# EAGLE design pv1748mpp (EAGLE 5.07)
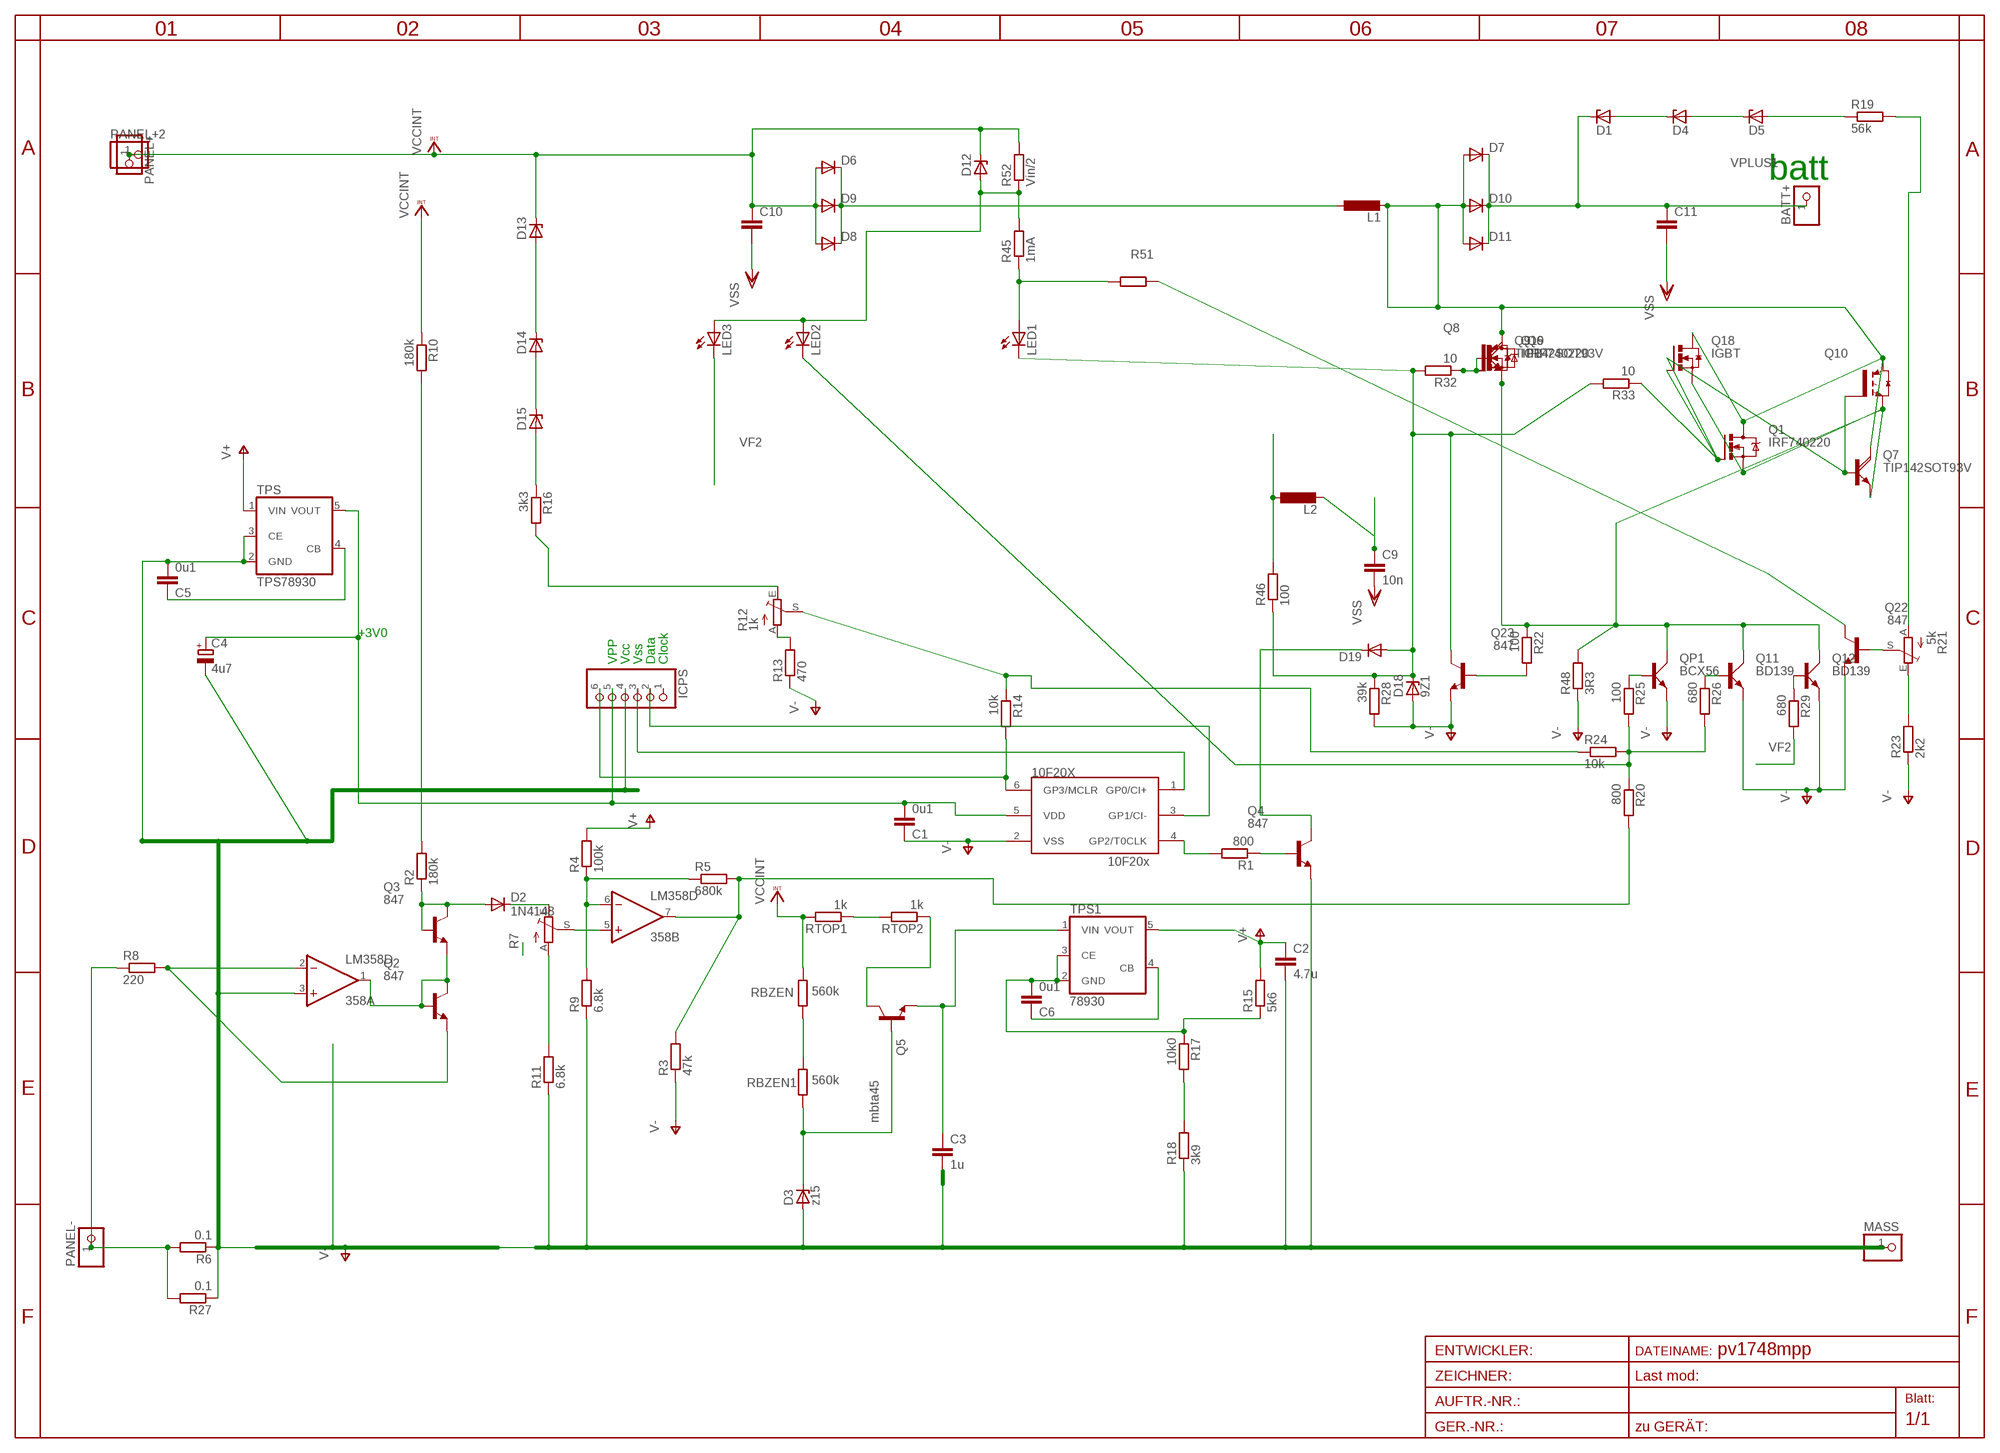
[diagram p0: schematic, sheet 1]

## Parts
10F20X  10F20x  PIC10F204OT  [SOT23-6]
358  LM358D  [SO08]
BATT+  PINHD-1X12MM3  [1X2MM3]
C1  0u1  C-EUC1206  [C1206]
C2  4.7u  C-EUC1206  [C1206]
C3  1u  C-EUC1206  [C1206]
C4  4u7  CPOL-EUSMCA  [SMC_A]
C5  0u1  C-EUC0805  [C0805]
C6  0u1  C-EUC0805  [C0805]
C9  10n  C-EUC0805  [C0805]
C10  C-EU075-052X106  [C075-052X106]
C11  C-EU075-052X106  [C075-052X106]
D1  ZENER-DIODESOD80C  [SOD80C]
D2  1N4148  DIODE-SOD80C  [SOD80C]
D3  z15  ZENER-DIODESOD80C  [SOD80C]
D4  ZENER-DIODESOD80C  [SOD80C]
D5  ZENER-DIODESOD80C  [SOD80C]
D6  DIODE-SMC  [SMC]
D7  DIODE-SMC  [SMC]
D8  DIODE-SMC  [SMC]
D9  DIODE-SMC  [SMC]
D10  DIODE-SMC  [SMC]
D11  DIODE-SMC  [SMC]
D12  ZENER-DIODESOD80C  [SOD80C]
D13  ZENER-DIODESOD80C  [SOD80C]
D14  ZENER-DIODESOD80C  [SOD80C]
D15  ZENER-DIODESOD80C  [SOD80C]
D18  9Z1  ZENER-DIODESOD80C  [SOD80C]
D19  DIODE-MINIMELF  [MINIMELF]
ICPS  PINHD-1X6  [1X06BOX]
L1  L-EUOPEN6  [OPEN6_3]
L2  L-EUOPEN6  [OPEN6_3]
LED1  LEDCHIPLED_1206  [CHIPLED_1206]
LED2  LEDCHIPLED_1206  [CHIPLED_1206]
LED3  LEDCHIPLED_1206  [CHIPLED_1206]
MASS  PINHD-1X12MM3  [1X2MM3]
PANEL+  PINHD-1X11MM6  [1X1MM8]
PANEL+2  PINHD-1X12MM3  [1X2MM3]
PANEL-  PINHD-1X12MM3  [1X2MM3]
Q1  IRF740220  [TO220BV]
Q2  847  BC847ALT1SMD  [SOT23]
Q3  847  BC847ALT1SMD  [SOT23]
Q4  847  BC847ALT1SMD  [SOT23]
Q5  mbta45  BC847ALT1SMD  [SOT23]
Q6  IRF740220  [TO220BV]
Q7  TIP142SOT93V  [SOT93V]
Q8  IRG4BC15UD-S  [D2PACK]
Q9  TIP142SOT93V  [SOT93V]
Q10  IRG4BC15UD-S  [D2PACK]
Q11  BD139  [TO126AV]
Q12  BD139  [TO126AV]
Q18  IGBT  N-HEXFET_DPAK-  [TO252]
Q19  IGBT  N-HEXFET_DPAK-  [TO252]
Q22  847  BC847ASMD  [SOT23]
Q23  847  BC847ASMD  [SOT23]
QP1  BCX56  [SOT223]
R1  800  R-EU_R0805  [R0805]
R2  180k  R-EU_0207/15  [0207/15]
R3  47k  R-EU_R0805  [R0805]
R4  100k  R-EU_R1206  [R1206]
R5  680k  R-EU_R0805  [R0805]
R6  0.1  R-EU_R2010  [R2010]
R7  TRIM_EU-S64W  [S64W]
R8  220  R-EU_R0805  [R0805]
R9  6.8k  R-EU_R1206  [R1206]
R10  180k  R-EU_R1206  [R1206]
R11  6.8k  R-EU_R0805  [R0805]
R12  1k  TRIM_EU-S64W  [S64W]
R13  470  R-EU_R0805  [R0805]
R14  10k  R-EU_R0805  [R0805]
R15  5k6  R-EU_R0805  [R0805]
R16  3k3  R-EU_R0805  [R0805]
R17  10k0  R-EU_R0805  [R0805]
R18  3k9  R-EU_R0805  [R0805]
R19  56k  R-EU_R0805  [R0805]
R20  800  R-EU_R0805  [R0805]
R21  5k  TRIM_EU-S64W  [S64W]
R22  100  R-EU_R0805  [R0805]
R23  2k2  R-EU_R0805  [R0805]
R24  10k  R-EU_R0805  [R0805]
R25  100  R-EU_R0805  [R0805]
R26  680  R-EU_R0805  [R0805]
R27  0.1  R-EU_R3216  [R3216]
R28  39k  R-EU_R0805  [R0805]
R29  680  R-EU_R0805  [R0805]
R32  10  R-EU_R0805  [R0805]
R33  10  R-EU_R0805  [R0805]
R45  1mA  R-EU_R1206  [R1206]
R46  100  R-EU_R0805  [R0805]
R48  3R3  R-EU_R2010  [R2010]
R51  39k  R-EU_R0805  [R0805]
R52  Vin/2  R-EU_R1206  [R1206]
RBZEN  560k  R-EU_R1206  [R1206]
RBZEN1  560k  R-EU_R1206  [R1206]
RTOP1  1k  R-EU_R1206  [R1206]
RTOP2  1k  R-EU_R1206  [R1206]
TPS  TPS78930  TPS78930SOT23-5  [SOT25]
TPS1  78930  TPS78930SOT23-5  [SOT25]

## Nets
BOOST_EN: D19.C Q4.3(C)
CB: D3.C Q5.1(B) RBZEN1.2
DQ18: D7.A D10.A D11.A L1.2 Q1.D Q6.D Q7.C Q8.2(C) Q9.C Q10.2(C) Q18.3(D) Q19.3(D)
GND1: C6.1 TPS1.4(CB)
IN-: PANEL-.1 R6.2 R8.1 R27.2
L2DOT: C9.1 L2.2
L2NO: L2.1 R46.2
N$1: Q4.1(B) R1.1
N$2: R7.A R11.2
N$3: R12.S R14.1 R24.1
N$4: 10F20X.1(GP0/CI+) ICPS.3
N$5: 10F20X.4(GP2/T0CLK) R1.2
N$6: R2.2 R10.2
N$7: 358.1(A:OUT) Q2.1(B) Q2.3(C) Q3.2(E)
N$8: 10F20X.3(GP1/CI-) ICPS.2
N$9: 10F20X.5(VDD) C1.2 C4.+ ICPS.5 TPS.5(VOUT)
N$10: 358.2(A:-IN) Q2.2(E) R8.2
N$11: C5.1 TPS.4(CB)
N$12: D2.A Q3.1(B) Q3.3(C) R2.1
N$13: D2.C R7.E
N$15: 358.5(B:+IN) R7.S
N$16: Q5.3(C) RTOP2.1
N$17: 358.6(B:-IN) R4.1 R5.1 R9.2
N$18: D15.A R16.1
N$19: RBZEN1.1 RBZEN.2
N$20: LED1.A R45.1 R51.1
N$21: Q23.1(B) R22.2
N$22: D5.A R19.1
N$23: D14.A D15.C
N$24: D13.A D14.C
N$25: R12.E R16.2
N$26: R12.A R13.2
N$27: QP1.1(B) R25.1
N$28: R17.2 R18.2
N$29: RTOP1.1 RTOP2.2
N$30: D4.A D5.C
N$31: D1.A D4.C
N$32: R19.2 R21.A
N$33: 358.7(B:OUT) R3.2 R5.2 R20.2
N$34: R21.E R23.2
N$35: Q11.B R26.1
N$36: Q12.B R29.1
N$56: Q1.G Q7.B Q10.1(G) Q18.1(G) R33.1
N$58: Q6.G Q8.1(G) Q9.B Q19.1(G) R32.1
N$71: Q22.3(C) R51.2
N$80: D12.A LED2.A LED3.A R45.2 R52.1
N$89: LED2.C R20.1 R24.2 R25.2 R26.2
NODOTL2: D6.C D8.C D9.C L1.1
PGATE: D18.C D19.A LED1.C Q23.3(C) R28.1 R32.2 R33.2 R46.1
PIR: 10F20X.6(GP3/MCLR) ICPS.6 R14.2
PRB1: Q22.1(B) R21.S
SFET1: Q1.S Q6.S Q7.E Q8.3(E) Q9.E Q10.3(E) Q11.C Q12.C Q18.2(S) Q19.2(S) QP1.2(C) R22.1 R48.2
V15: C3.1 Q5.2(E) TPS1.1(VIN)
V+: C2.1 R4.2 R15.2 TPS1.5(VOUT) TPS.1(VIN)
V-: 10F20X.2(VSS) 358.3(A:+IN) C1.1 C2.2 C3.2 C4.- C5.2 C9.2 C10.2 C11.2 D3.A D18.A ICPS.4 MASS.1 Q4.2(E) Q11.E Q12.E Q22.2(E) Q23.2(E) QP1.3(E) R3.1 R6.1 R9.1 R11.1 R13.1 R18.1 R23.1 R27.1 R28.2 R48.1 TPS.2(GND) TPS.3(CE) ; supply symbol labelled VSS
VCCINT: C10.1 D6.A D8.A D9.A D12.C D13.C PANEL+2.1 PANEL+.1 R10.1 R52.2 RBZEN.1 RTOP1.2
VF2: LED3.C R29.2
VPLUS1: BATT+.1 C11.1 D1.C D7.C D10.C D11.C
X: C6.2 R15.1 R17.1 TPS1.2(GND) TPS1.3(CE)
Unconnected: ICPS.1

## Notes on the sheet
- batt
- +3V0
- VPP | Vcc | Vss | Data | Clock

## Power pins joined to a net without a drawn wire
V+: 358.8(P:V+)
V-: 358.4(P:V-)

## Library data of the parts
10F20X = microchip-3:PIC10F2*: uPC nW 0,25/0,5k Program Flash memory Comparator
358 = linear:LM358: OP AMP also LM158; LM258; LM2904 Source: http://cache.national.com/ds/LM/LM158.pdf
BATT+ MASS PANEL+ PANEL+2 PANEL- = pinhead:PINHD-1X1: PIN HEADER
C1-C3 C5 C6 C9-C11 = rcl:C-EU: CAPACITOR, European symbol
C4 = rcl(2):CPOL-EU: POLARIZED CAPACITOR, European symbol
D1 D3-D5 D12-D15 D18 = diode:ZENER-DIODE: Z-Diode
D2 D6-D11 D19 = diode:DIODE-: DIODE
ICPS = pinhead:PINHD-1X6: PIN HEADER
L1 L2 = rcl:L-EU: INDUCTOR, European symbol
LED1-LED3 = led:LED: LED
Q1 Q6 = transistor-power:IRF740: N-CHANNEL MOS FET
Q2-Q5 Q22 Q23 = transistor-npn:BC847*: NPN Transistor
Q7 Q9 = transistor-power:TIP142: NPN DARLINGTON TRANSISTOR
Q8 Q10 = transistor-power:IRG4BC15UD-: INSULATED GATE BIPOLAR TRANSISTOR WITH ULTRAFAST SOFT RECOVERY DIODE
Q11 Q12 = transistor-power:BD139: NPN TRANSISTOR
Q18 Q19 = transistor-power:N-HEXFET_?-*: HEXFET® Power MOSFET
QP1 = transistor-power:BCX56
R1-R6 R8-R11 R13-R20 R22-R29 RBZEN RBZEN1 RTOP1 RTOP2 = rcl:R-EU_: RESISTOR, European symbol
R7 R12 R21 = pot:TRIM_EU-: POTENTIOMETER
R32 R33 R45 R46 R48 R51 R52 = rcl-2:R-EU_: RESISTOR, European symbol
TPS TPS1 = v-reg:TPS78930

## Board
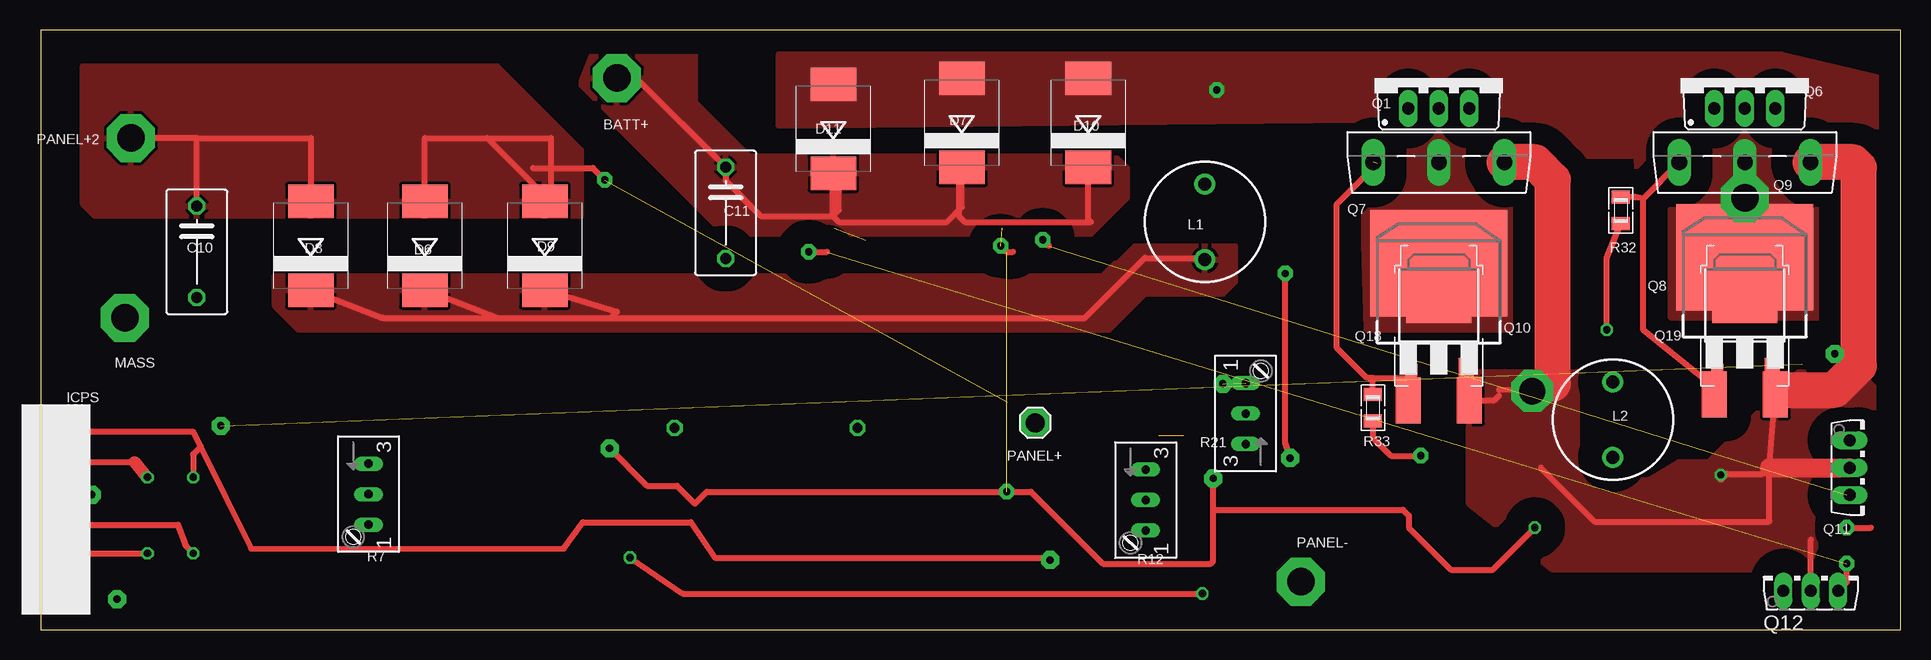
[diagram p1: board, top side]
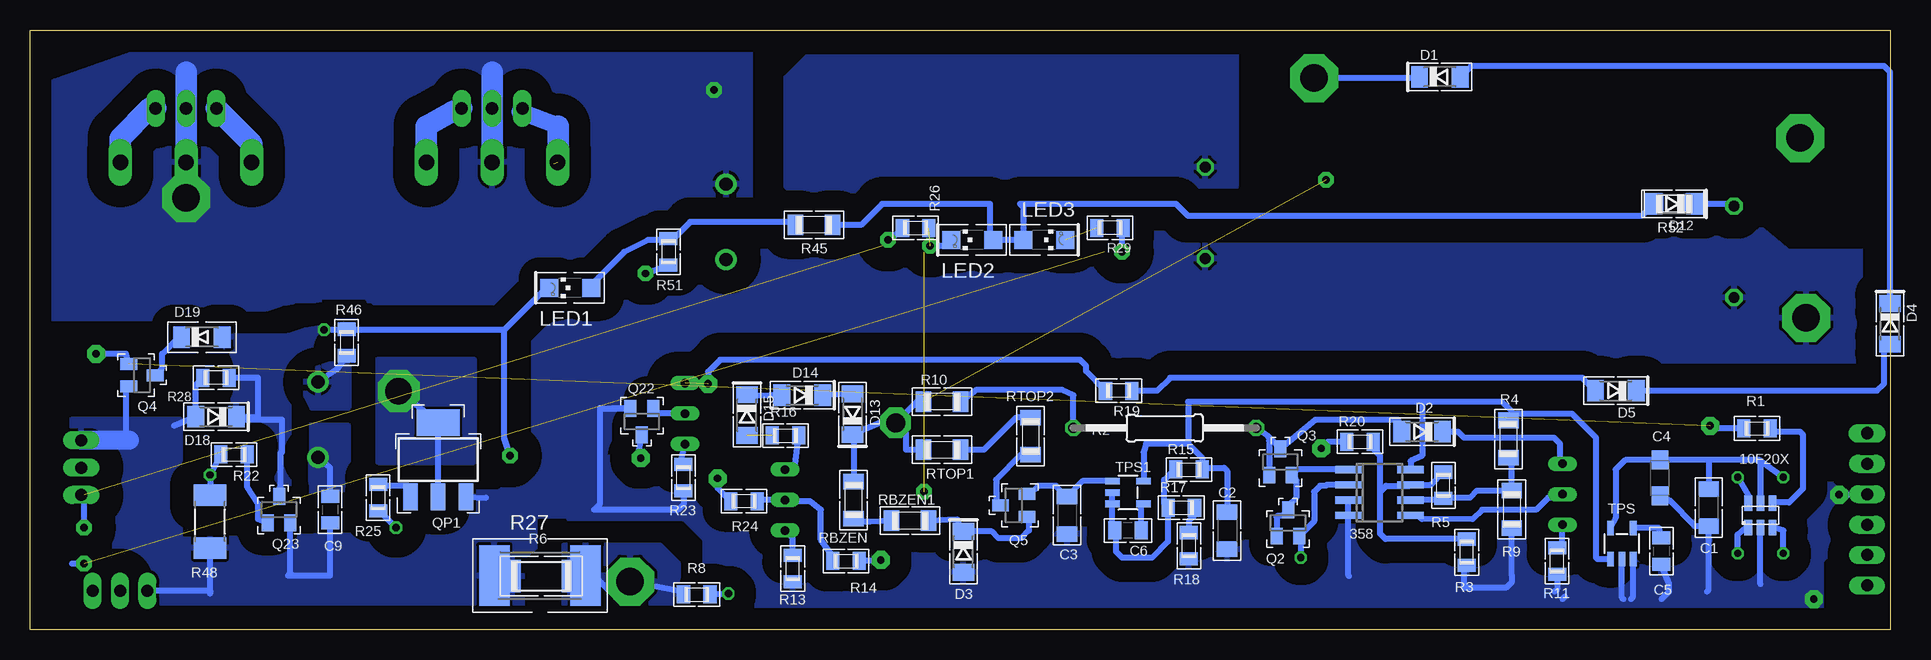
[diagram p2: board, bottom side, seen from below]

Size 155 x 50 mm. Coordinates in mm from the lower left corner, seen from the top.
Outline: 0,0 155,0 155,50 0,50 0,0
Copper layers (1*16): Top 0.035mm / dielectric 1.5mm / Bottom 0.035mm
Design rules "default *": minimum track width 10mil, minimum drill 24mil, track to track 8mil, track to pad 8mil, pad to pad 8mil, via to via 8mil, smd to smd 8mil, copper to edge 30mil, drill to drill 8mil, minimum pad ring 10mil, minimum via ring 8mil, stop-mask expansion 4mil, vias tented up to drill 0mil, thermal gap 10mil

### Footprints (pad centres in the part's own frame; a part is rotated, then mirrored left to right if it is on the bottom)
SOT23-6 = smd 0.635 x 1.27: 1 -1.016,-1.016; 2 0,-1.016; 3 1.016,-1.016; 4 1.016,1.016; 5 0,1.016; 6 -1.016,1.016
SO08 = smd 0.6 x 2.2: 1 -1.905,-2.6; 2 -0.635,-2.6; 3 0.635,-2.6; 4 1.905,-2.6; 5 1.905,2.6; 6 0.635,2.6; 7 -0.635,2.6; 8 -1.905,2.6
1X2MM3 = drill 2.3 pad 4 octagon: 1 0,0
C1206 = smd 1.3 x 1.7: 1 -1.55,0; 2 1.55,0
SMC_A = smd 1.6 x 1.4: + -1.5,0; - 1.5,0
C0805 = smd 1.1 x 1.5: 1 -1.1,0; 2 1.1,0
C075-052X106 = drill 0.914 octagon: 1 -3.81,0; 2 3.81,0
SOD80C = smd 1.4 x 1.8: A 1.7,0; C -1.7,0
SMC = smd 2.8 x 3.8: A 3.7,0; C -3.7,0
MINIMELF = smd 1.4 x 1.8: A 1.7,0; C -1.7,0
1X06BOX = drill 1 long: 1 -6.35,0; 2 -3.81,0; 3 -1.27,0; 4 1.27,0; 5 3.81,0 | drill 1.016 long: 6 6.35,0
OPEN6_3 = drill 1.1 pad 1.778 round: 1 -3.15,0; 2 3.15,0
CHIPLED_1206 = smd 1.5 x 1.5: A 0,-1.75; C 0,1.75
1X1MM8 = drill 1.6 pad 2.54 octagon: 1 0,0
TO220BV = drill 1.016 long: D 0,-2.54; G -2.54,-2.54; S 2.54,-2.54
SOT23 = smd 1 x 1.4: 1 -0.95,-1.1; 2 0.95,-1.1; 3 0,1.1
SOT93V = drill 1.3 pad 1.676 long: B -5.461,-2.54; C 0,-2.54; E 5.461,-2.54
D2PACK = smd 2.083 x 3.81: 1 -2.54,-8.89; 3 2.54,-8.89 | smd 11.43 x 8.89: 2 0,2.54
TO126AV = drill 1 pad 1.27 long: B 2.286,-1.27; C 0,-1.27; E -2.286,-1.27
TO252 = smd 1 x 1.6: 1 -2.28,-3.53 | smd 1.27 x 2.54: 2 2.28,-3.53 | smd 5.4 x 6.2: 3 0,3.77
SOT223 = smd 1.219 x 2.235: 1 -2.311,-3.099; 2 0,-3.099; 3 2.311,-3.099 | smd 3.6 x 2.2: 4 0,3.099
R0805 = smd 1.1 x 1.5: 1 -1.1,0; 2 1.1,0
0207/15 = drill 0.813 octagon: 1 -7.62,0; 2 7.62,0
R1206 = smd 1.3 x 1.7: 1 -1.55,0; 2 1.55,0
R2010 = smd 1.4 x 2.7: 1 -2.4,0; 2 2.4,0
S64W = drill 0.7 long: A 2.54,1.27; E -2.54,1.27; S 0,1.27
R3216 = smd 2.54 x 5.08: 1 -3.81,0; 2 3.81,0
R2010' = smd 1.8 x 2.7: 1 -2.2,0; 2 2.2,0
SOT25 = smd 0.55 x 1.2: 1 -0.95,-1.3; 2 0,-1.3; 3 0.95,-1.3; 4 0.95,1.3; 5 -0.95,1.3

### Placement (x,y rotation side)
10F20X  10.79,9.53 0 bottom
358  42.55,11.43 270 bottom
BATT+  48,46 0 top
C1  15.11,10.16 90 bottom
C2  55.24,8.26 270 bottom
C3  68.58,9.53 270 bottom
C4  19.18,12.63 270 bottom
C5  19.05,6.54 270 bottom
C6  63.5,8.26 180 bottom
C9  130,10 270 bottom
C10  13,31.5 270 top
C11  57.06,34.75 270 top
D1  37.51,46.09 0 bottom
D2  39,16.5 180 bottom
D3  77.22,6.48 270 bottom
D4  0,25.5 270 bottom
D5  22.84,19.91 180 bottom
D6  32,32 90 top
D7  76.77,42.25 90 top
D8  22.5,32 90 top
D9  42,32 90 top
D10  87.29,42.25 90 top
D11  66.05,41.75 90 top
D12  18,35.5 180 bottom
D13  86.45,17.96 90 bottom
D14  90.65,19.55 180 bottom
D15  95.27,17.88 270 bottom
D18  139.5,17.75 180 bottom
D19  140.67,24.38 0 bottom
ICPS  1.91,10.02 90 top
L1  97,34 90 top
L2  131,17.5 270 top
LED1  110,28.5 90 bottom
LED2  76.5,32.5 90 bottom
LED3  70.5,32.5 270 bottom
MASS  7,26 0 top
PANEL+  82.86,17.24 0 top
PANEL+2  7.5,41 0 top
PANEL-  105,4 0 top
Q1  116.5,46 0 top
Q2  50.16,8.89 0 bottom
Q3  50.8,13.97 0 bottom
Q4  145.67,21.2 270 bottom
Q5  73.03,10.35 90 bottom
Q6  142,46 0 top
Q7  116.5,41.5 0 top
Q8  142,28.5 0 top
Q9  142,41.5 0 top
Q10  116.5,28 0 top
Q11  152,13.5 270 top
Q12  147.5,4.5 0 top
Q18  116.5,24.9 0 top
Q19  142,24.9 0 top
Q22  104.01,17.34 180 bottom
Q23  134.25,10 0 bottom
QP1  120.98,14.16 0 bottom
R1  11.08,16.77 0 bottom
R2  60.44,16.81 180 bottom
R3  35.27,6.45 90 bottom
R4  31.8,15.88 90 bottom
R5  37.22,12.03 90 bottom
R6  112.39,4.45 0 bottom
R7  26.04,11.29 270 top
R8  99.44,2.92 0 bottom
R9  31.52,10.03 90 bottom
R10  79,19 0 bottom
R11  27.75,5.71 90 bottom
R12  90.81,10.79 270 top
R13  91.44,5.08 90 bottom
R14  87,5.71 0 bottom
R15  58.42,13.34 0 bottom
R16  92.05,16.18 0 bottom
R17  59.05,10.16 0 bottom
R18  58.42,6.99 90 bottom
R19  64.28,19.91 180 bottom
R20  44.16,15.66 0 bottom
R21  101.68,18.01 90 top
R22  138,14.6 0 bottom
R23  100.55,12.66 90 bottom
R24  95.5,10.7 180 bottom
R25  126,11 270 bottom
R26  81.2,33.5 0 bottom
R27  112.5,4.5 0 bottom
R28  139.5,21 180 bottom
R29  65,33.5 180 bottom
R32  131.66,34.95 270 top
R33  111,18.5 270 top
R45  89.67,33.75 0 bottom
R46  128.61,23.94 270 bottom
R48  3R3  [R2010']  140,9 90 bottom
R51  101.8,31.5 270 bottom
R52  18,35.5 0 bottom
RBZEN  86.36,10.79 270 bottom
RBZEN1  81.66,9.07 0 bottom
RTOP1  79,15 180 bottom
RTOP2  71.62,16.12 90 bottom
TPS  22.35,7.17 0 bottom
TPS1  63.5,11.43 270 bottom

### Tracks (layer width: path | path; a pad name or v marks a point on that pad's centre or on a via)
BOOST_EN
  Bottom 0.5: D19.C 142.62,24.38 144,23 144,21.77 Q4.3
CB
  Bottom 0.5: Q5.1 71.75,9.23 71.75,8.26 72.39,7.62 74.3,7.62 74.85,8.18 D3.C 77.72,9.18 RBZEN1.2
DQ18  (via drill 0.6 pad 1.27, 2.3 pad 4)
  Bottom 1.8: Q7.C Q1.D 116.5,46.5 | Q9.C Q6.D 142,46.5
  other vias: 142,36 98,45
  pour Bottom (isolate 1.8, rank 4): 95,36 95,48.5 145,48.5 153.5,45.5 153.5,26 134.5,26 133,27.5 126.5,27.5 125.5,26.5 111.5,26
  pour Top (isolate 1.8, rank 4, no thermals): 61.5,42 61.5,48 145,48 153.5,46 153.5,26 134.5,26 133.5,27 133,39.5 127.5,39.5 126.5,38.5 126.5,27 124.5,25 110.5,25 110,42.5
GND1
  Bottom 0.5: C6.1 62.4,10.28 TPS1.4
IN-
  Bottom 0.5: R6.2 107.95,4.45 106.68,3.17 PANEL-.1 100.8,3.17 R8.1
  pour Bottom (isolate 2): 101,1 101,5.5 102.5,7 110.5,7 110.5,1.5 110,1
L2DOT
  Bottom 0.5: L2.2 130,13.5 C9.1
  pour Bottom (isolate 2, rank 3, no thermals): 128.5,11 128.5,17 132,17 132,11
L2NO
  Bottom 0.5: R46.2 129.41,21.72 L2.1
  pour Bottom (isolate 2, rank 3): 129,22.5 128.5,22 128.5,18.5 131.5,18.5 132,19.5 132,21.5
N$1  (via drill 0.6 pad 1.5)  (1 unrouted)
  Bottom 0.5: Q4.1 147,23 v149.5,23 | R1.1 14.77,16.77 v15,17
N$2
  Bottom 0.5: R7.A 27.3,7.26 R11.2
N$3
  Bottom 0.5: R14.1 88.09,6.09 89.1,7.5 89.1,10 90,10.7 91.87,10.7 R12.S 94,10.8 R24.1
N$4  (via drill 0.6)
  Top 0.5: ICPS.3 11.43,8.75 12.06,6.99 v12.7,6.35
  Bottom 0.5: v12.7,6.35 12.7,7.9 11.99,8.51 10F20X.1
N$5
  Bottom 0.5: 10F20X.4 9.72,10.6 8.4,10.6 7.24,11.76 7.24,16.24 7.5,16.5 9.71,16.5 R1.2
N$6
  Bottom 0.5: R2.2 68.06,19.56 69,20 76.14,20 R10.2
N$7
  Bottom 0.5: 358.1 49.38,13.34 Q3.2 49.5,12.52 49.5,11 50.16,10.34 Q2.3 50.66,9.5 51,9.5 51.12,9.38 Q2.1
N$8  (via drill 0.6)
  Top 0.5: ICPS.2 3.67,6.21 3.81,6.35 v8.89,6.35
  Bottom 0.5: v8.89,6.35 8.89,8.26 10F20X.3
N$9  (via drill 0.6)
  Top 0.5: 7.81,13.97 2.04,13.97 ICPS.5
  Top 1.016: 7.81,13.97 v8.89,12.7
  Bottom 0.5: 15.24,14.13 10.86,14.13 10.75,14.02 | 15.24,14.13 C4.+ 22.06,14.13 22.86,13.34 22.86,9.3 TPS.5 | v8.89,12.7 10.7,13.97 10.75,14.02 | 10F20X.5 10.79,13.97 10.75,14.02 | C1.2 15.11,14 15.24,14.13
N$10  (via drill 0.6)
  Top 0.5: v96.8,3 53.5,3 v49.1,6
  Bottom 0.5: 358.2 46.94,12.06 47,12 47.5,12 48,11.5 48,9.01 Q2.2 49.1,7.41 v49.1,6 | R8.2 97.08,2.92 v96.8,3
N$11
  Bottom 0.5: TPS.4 19.25,8.47 C5.1
N$12
  Bottom 0.5: D2.A 41,17.5 47.88,17.5 Q3.3 51.62,15.88 | R2.1 51.82,16.09 51.62,15.88 | Q3.1 51.75,15.75 51.62,15.88
N$13
  Bottom 0.5: D2.C 35.99,16.49 35.5,16 28,16 27.5,15.5 27.5,14.03 R7.E
N$15
  Bottom 0.5: 358.5 39.52,9.53 39,9.2 34.77,9.22 34,10 29.5,10 28.5,11 27.59,11 R7.S
N$16
  Bottom 0.5: RTOP2.1 72.43,14.57 74.5,12.5 74.5,10.73 Q5.3
N$17
  Bottom 0.5: 358.6 37.35,10.79 R5.1 37.15,11 35,11 34.42,11.57 R9.2 31.52,14.05 R4.1
N$18  (1 unrouted)
N$19
  Bottom 0.5: RBZEN1.1 83.37,9.07 85,9 86.11,9 RBZEN.2
N$20
  Bottom 0.5: LED1.A 108.25,28.75 105.5,31.5 103.5,32.5 102.5,32.5 101.9,32.5 | 101.9,32.5 R51.1 | R45.1 91.47,34 100,34 101.5,32.5 101.9,32.5
N$21
  Bottom 0.5: R22.2 136.9,11.9 136,10.5 136,9.2 Q23.1
N$22
  Bottom 0.5: D5.A 25.64,21 60,21 61.09,19.91 R19.1
N$23
  Bottom 0.5: D14.A 95.43,19.45 D15.C
N$24
  Bottom 0.5: D13.A D14.C
N$25
  Bottom 0.5: R16.2 91.25,13.76 R12.E
N$26
  Bottom 0.5: R13.2 91.44,7.62 R12.A
N$27
  Bottom 0.5: QP1.1 123.3,11.3 123.5,12 125.6,12 R25.1
N$28
  Bottom 0.5: R18.2 58.42,9.08 58,9.5 58,10.12 R17.2
N$29
  Bottom 0.5: RTOP1.1 75.52,14.98 72.83,17.67 RTOP2.2
N$30
  Bottom 0.5: D4.A 0.5,23.3 0.5,20.5 1.09,19.91 D5.C
N$31
  Bottom 0.5: D1.A 34.9,47 0.5,47 0,46.5 D4.C
N$32  (via drill 0.6 pad 1.5)  (1 unrouted)
  Bottom 0.5: R19.2 67,21.53 67,22 67.5,22.5 97.5,22.5 98.5,21.5 v98.5,20.5
N$33
  Bottom 0.5: R5.2 38.28,12.06 358.7 40.01,12 42,12 42.5,11.5 | R3.2 42.05,7.54 42.5,8 42.5,11.5 | 42.5,11.5 42.5,14.5 43,15 43,15.6 R20.2
N$34
  Bottom 0.5: R21.E 100.75,13.97 R23.2
N$35  (via drill 0.6 pad 1.27)  (1 unrouted)
  Top 0.5: v150.5,8.5 152.5,8.5 | v83.5,32.5 84,32
  Bottom 0.5: Q11.B 150.5,11.21 v150.5,8.5 | R26.1 83.3,32.5 v83.5,32.5
N$36  (via drill 0.6 pad 1.27)  (1 unrouted)
  Top 0.5: v64,31.5 65.5,31.5 | Q12.B 150.5,3.94 v150.5,5.5
  Bottom 0.5: R29.1 64,33.4 v64,31.5 | v150.5,5.5 151.5,5.5
N$56  (1 unrouted)
  Top 0.5: Q10.1 114.06,19.21 Q18.1 113.85,21 111,21 | 111.36,38.86 108,35.5 108,23.5 110.5,21 111,21 | R33.1 111,21
  Bottom 0.5: Q1.G 114.18,43.46 114.18,43.18
  Bottom 1.4: 111,42 114.18,43.18
  Bottom 1.8: 111,42 111,39.86 Q7.B
N$58
  Top 0.5: 133.54,35.93 Q9.B | 133.54,35.93 133.54,24.96 138.5,21 Q19.1 139.59,20.25 Q8.1 | R32.1 132.91,36.05 133.54,35.93
  Bottom 1.8: Q9.B 136.54,40.54 Q6.G
N$71  (via drill 0.6 pad 1.27, 0.6 pad 1.5)
  Top 0.5: v103.7,29.7 103.7,15.6 v104.1,14.3
  Bottom 0.5: v103.7,29.7 R51.2 | v104.1,14.3 104.25,15 Q22.3
N$80
  Bottom 0.5: R52.1 D12.A 20.7,34.5 58.5,34.5 59.5,35.5 72.5,35.5 72.25,35.25 LED3.A LED2.A 75,32.75 75,35.5 84,35.5 85.75,33.75 R45.2
N$89  (via drill 0.6, 0.6 pad 1.27, 0.6 pad 1.5)  (2 unrouted)
  Top 0.5: v47.4,15.1 50.5,12 53,12 54.5,10.5 55.5,11.5 v80.5,11.5 82.5,11.5 88.5,5.5 97.5,5.5 97.7,5.7 97.7,10 | 97.7,10 v97.7,12.6 | v124.5,8.5 121,5 117.5,5 114,8.5 114,9.5 113.5,10 97.7,10 | v80,32 80.5,31.5 81,31.5
  Bottom 0.5: R24.2 97.7,11.8 v97.7,12.6 | v47.4,15.1 46.84,15.66 R20.1 | LED2.C 78.75,32 v80,32 | v124.5,8.5 125.9,9.9 R25.2
NODOTL2
  Top 0.5: D8.C 28.5,26 38,26 | 38,26 47.5,26 | 47.5,26 87,26 92,31 96.85,31 L1.1 | 38,26 D6.C | D9.C 48,26.5 47.5,26
  pour Top (isolate 2, rank 3): 19.5,29.5 88.5,29.5 91,32 99.5,32 99.5,29 98.5,28 92,28 89,25 21.5,25 19.5,27
PGATE  (via drill 0.6, 0.6 pad 1.27)
  Top 0.5: R32.2 130.5,31 v130.5,25 | R33.2 111,16 112.5,14.5 v115,14.5
  Bottom 0.5: R46.1 v130.5,25 115.5,25 | Q23.3 134.25,11.75 134.1,11.8 134.1,14.8 134,14.8 134,17.5 137.8,17.5 D18.C 136,17.75 136,21 R28.1 | v115,14.5 115.5,16 115.5,25 | LED1.C 112,28.5 115.5,25
  pour Bottom (isolate 2, rank 3): 135,11 135,15 136,16 137,16 138.5,17.5 138.5,19.5 139,21.5 139.5,24.5 133.5,24.5 132,25 129,25.5 129,24 133.5,22.5 133.5,11.5
PIR  (via drill 0.6, 0.6 pad 1.5)
  Top 0.5: 13.34,15.24 17.54,6.74 43.58,6.77 45.17,8.95 54.17,8.95 56.17,5.98 83.92,5.98 v84.1,5.8 | 13.34,15.24 12.7,16.51 2.04,16.51 ICPS.6 | v12.7,12.7 12.7,14.61 13.34,15.24
  Bottom 0.5: 10F20X.6 11.81,11.18 v12.7,12.7 | R14.2 84.58,5.71 v84.1,5.8
PRB1
  Bottom 0.5: R21.S 102.99,18.01 Q22.1
SFET1  (via drill 0.6, 2.2 pad 3.5)
  Top 0.5: Q8.3 144.04,13.5 144.04,9.04 144,9 129.5,9 125,13.5 | v140,12.9 140,12.5 140.5,13 143.5,13 144,13.5 | Q19.2 144.16,20.84 145,20 | Q18.2 118.78,19.37 Q10.3 121.11,19.11 121.5,19.5 | v124.28,19.89 121.5,20 | Q12.C 147.5,7.5
  Top 1.6: 144.04,13.5 Q11.C
  Top 3: Q7.E 124.54,38.96 126,37.5 126,20.5 | Q9.E 151.04,38.96 151.5,38.5 151.5,22 149.5,20 145,20
  Bottom 0.5: R48.2 v140,12.9 R22.1 | QP1.2 120.98,17.29 v124.28,19.89
  Bottom 1.8: Q1.S 119.82,43.18 122,42 122,38.93 Q7.E | Q6.S 145.04,43.46 147.5,41 147.5,39 Q9.E
  pour Bottom (no thermals): 126,22.5 126,14 118,14 118,22.5
  pour Top (isolate 2, rank 3): 119,21.5 128,21.5 128,14 129.5,12.5 134,12.5 136.5,14 139,14 146.5,21.5 151.5,21.5 153,20 153,11.5 149.5,5 126,5 119,10.5
V15
  Bottom 0.5: TPS1.1 67.28,12.38 C3.1 69.5,12 71,12 71.7,11.3 Q5.2
V+
  Bottom 0.5: TPS.1 24.38,5.88 24.5,6 24.5,16 26.5,18 31.5,18 31.5,18.18 | 31.5,18.18 R4.2 | 39,19 32.32,19 31.5,18.18 | 39,19 58.5,19 58.5,15.5 | C2.1 55.24,13.24 55.5,13.5 57.16,13.5 R15.2 57.32,14.32 58.5,15.5 | TPS1.5 62.2,14.8 62,15.5 58.5,15.5 | 358.8 39.95,14.05 39,14.5 39,19
V-  (via drill 0.6 pad 1.5)
  Top 0.5: ICPS.4 2.04,11.43 | v4.25,11.25 1.91,11.25
  Bottom 0.5: 15.24,3.17 15.11,3.31 C1.1 16.23,8.62 18.41,10.79 18.84,10.79 C4.- | 10.79,3.81 10F20X.2 | C5.2 18.41,3.81 18.41,3.17 19.05,2.54 | 27.3,2.54 27.08,2.77 | TPS.3 21.4,2.73 21.59,2.54 | 22.23,2.54 22.35,2.67 TPS.2 | R11.1 27.75,3.37 27.94,3.17 | 45.09,4.45 45.15,4.5 358.4 358.3 | v4.25,11.25 2.04,11.25 ICPS.4 | R9.1 31.52,4.53 31.5,4.5 31.5,4 32,3.5 35.5,3.5 35.5,5.12 R3.1 | 106.44,18.44 Q22.2 107.44,18.44 107.5,18.5 107.5,10.5 108,10 101,10 100.5,10.5 100.5,11.52 R23.1 | Q23.2 133.3,4.7 133.5,4.5 130,4.5 C9.2 | 143,17 D18.A 141.2,20.4 R28.2 | QP1.3 117,11 | Q4.2 147,20.25 147,16.5 | 140,3.23 Q12.E | 140,3.23 140,3 | 140,3.23 140,6
  Bottom 1.6: 146.7,15.79 Q11.E
  other vias: 6.35,2.54
  pour Bottom (isolate 1.8, rank 2): 1.27,12.06 6.35,12.06 7.62,10.79 7.62,9.53 8.89,8.26 11.43,8.26 11.43,6.99 13.34,9 95.5,8 106.5,15 110.22,9.5 106.68,3.81 106.68,-0.64 106.05,-1.27 8.26,-1.27 5.71,1.27 5.71,5.71 5.08,6.35
  pour Bottom (isolate 2, rank 2): 11.5,34 96.5,34 116.5,22.5 116.5,12.5 123.5,8 142.5,7.5 142.5,17.5 151.5,17.5 151.5,2 114,2 114,6 110.5,9 103,21 1,21 0,22 0,25.5 0.5,31.5 8.5,31.5
VCCINT  (via drill 0.6 pad 1.27)  (1 unrouted)
  Top 0.5: 13,41 PANEL+2.1 | 13,41 22.5,41 D8.A | C10.1 13,41 | D6.A 32,41 37.2,41 | 42.5,35.7 D9.A | 42.5,35.7 42.5,41 37.2,41 | 37.2,41 42.5,35.7 | v47,37.5 46,38.5 41,38.5
  Bottom 0.5: PANEL+.1 83.86,17.34 D13.C 86.36,16.16 RBZEN.1 | D12.C R52.2 13,35.5 C10.1 | PANEL+.1 82,16.38 82,15 RTOP1.2 | PANEL+.1 81.1,19 R10.1
  pour Top (isolate 2, rank 2): 3.5,47 38,47 45,40 45,34.5 4.5,34.5 3.5,35.5
VF2  (1 unrouted)
VPLUS1
  Top 0.5: D10.C 87.29,34.21 87.5,34 77,34 76.5,34.5 76.5,38.28 D7.C 76.77,35.27 75.5,34 66.5,34 66,34.5 | 66,34.5 66,37 | 66,37 66,38.01 D11.C | 66,34.5 60,34.5 57.06,37.44 C11.1 49.62,46 BATT+.1 | 66,34.5 66.5,35 66.5,36.5 66,37
  Bottom 0.5: D1.C 39.3,46 BATT+.1
  pour Bottom (isolate 2): 54.5,48 90,48 92,46 92,37 90.5,35.5 90,35.5 89.5,35 56.5,35 54.5,37
  pour Top (isolate 2): 46,48 54.5,48 54.5,44 59,39.5 89.5,39.5 90.5,38.5 90.5,36 87.5,33 57,33 48,42 48,42.5 45,45.5
X
  Bottom 0.5: R15.1 59.66,13.34 60.5,12.5 60.5,10.51 R17.1 60.16,7.34 61.5,6 64,6 64.5,6.5 64.5,8.15 C6.2 64.8,8.46 TPS1.3 TPS1.2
